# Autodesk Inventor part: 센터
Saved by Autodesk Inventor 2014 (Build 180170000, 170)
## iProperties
Created: 2026-09
Part Number: 센터
Material: 일반
Document SubType Name: Modeling
Designer: dg
Density: 1 g/cm^3
Appearance: 기본값
Author: dg
Author: jhkim
Creation Date: 2026-08-27
Sending System: Autodesk Inventor 2027
Preprocessor: ST-DEVELOPER v20.1
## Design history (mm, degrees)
node "센터1"
node "솔리드1"
node "기준1"
